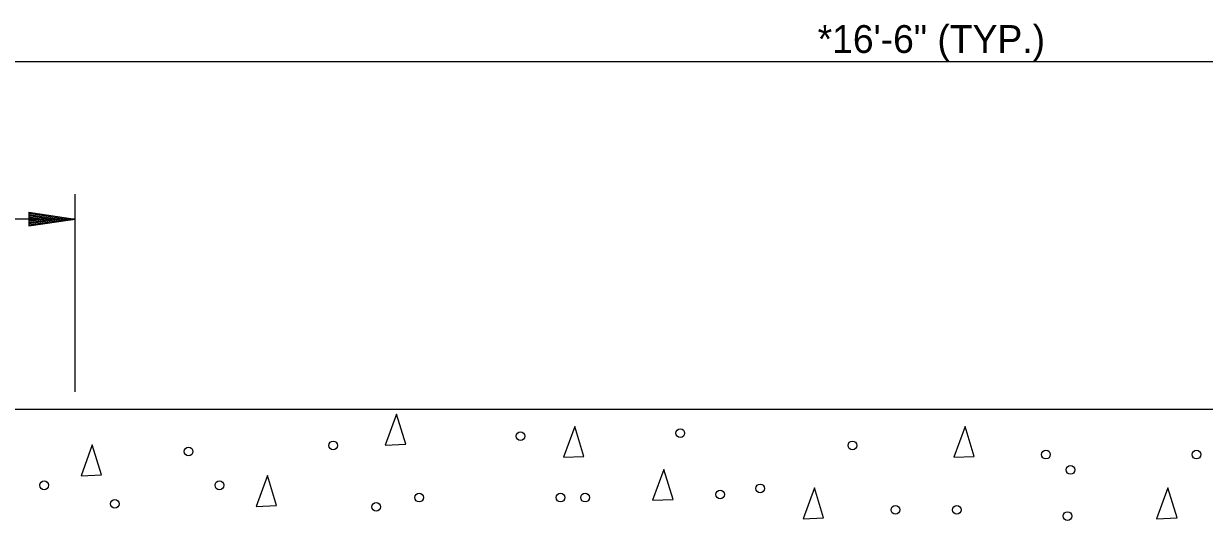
# Model space of a CAD drawing. Extents: x 635488 to 635865, y 290537 to 290973.
# Drawn here: x 635712.22 to 635737.65, y 290610.59 to 290621.3 of the extents above; entities that cross this region are included whole.
import ezdxf

# ---------------------------------------------------------------- set-up
doc = ezdxf.new("R2010")
doc.units = 0
doc.layers.add('Default', color=7, linetype='Continuous')

msp = doc.modelspace()

# ---------------------------------------------------------------- linework, layer by layer
at = {"layer": 'Default'}
for p, q in [((635709.583, 290620.481), (635750.831, 290620.481)), ((635713.333, 290613.362), (635713.333, 290617.625)), ((635712.334, 290617.236), (635713.334, 290617.086)), ((635712.334, 290617.236), (635712.334, 290616.936)), ((635713.333, 290617.086), (635709.583, 290617.086)), ((635712.334, 290617.211), (635713.167, 290617.086)), ((635712.334, 290617.186), (635712.994, 290617.086)), ((635712.334, 290617.161), (635712.829, 290617.086)), ((635712.334, 290617.136), (635712.659, 290617.086)), ((635712.334, 290617.111), (635712.492, 290617.086)), ((635712.334, 290616.936), (635713.334, 290617.086)), ((635712.334, 290617.038), (635712.659, 290617.086)), ((635712.334, 290616.986), (635712.994, 290617.086)), ((635712.334, 290616.961), (635713.167, 290617.086)), ((635712.334, 290617.011), (635712.829, 290617.086)), ((635712.334, 290617.063), (635712.492, 290617.086))]:
    msp.add_line(p, q, dxfattribs=at)
for points in [[(635659.586, 290612.987), (635750.831, 290612.987)], [(635720.254, 290612.878), (635720.011, 290612.216), (635720.451, 290612.233), (635720.254, 290612.878)], [(635724.091, 290612.613), (635723.849, 290611.951), (635724.289, 290611.968), (635724.091, 290612.613)], [(635732.496, 290612.613), (635732.256, 290611.951), (635732.696, 290611.968), (635732.496, 290612.613)], [(635713.702, 290612.218), (635713.459, 290611.553), (635713.899, 290611.571), (635713.702, 290612.218)], [(635726.011, 290611.688), (635725.769, 290611.024), (635726.208, 290611.041), (635726.011, 290611.688)], [(635717.474, 290611.556), (635717.232, 290610.891), (635717.672, 290610.909), (635717.474, 290611.556)], [(635729.253, 290611.291), (635729.011, 290610.626), (635729.451, 290610.644), (635729.253, 290611.291)], [(635736.865, 290611.291), (635736.623, 290610.626), (635737.063, 290610.644), (635736.865, 290611.291)]]:
    msp.add_lwpolyline(points, dxfattribs=at)
for centre in [(635722.924, 290612.407), (635726.365, 290612.473), (635715.776, 290612.075), (635718.887, 290612.208), (635730.071, 290612.208), (635734.24, 290612.009), (635737.483, 290612.009), (635734.769, 290611.678), (635712.666, 290611.347), (635716.438, 290611.347), (635720.74, 290611.082), (635723.784, 290611.082), (635724.313, 290611.082), (635727.225, 290611.148), (635728.085, 290611.281), (635714.188, 290610.95), (635719.813, 290610.884), (635730.997, 290610.817), (635732.321, 290610.817), (635734.703, 290610.685)]:
    msp.add_circle(centre, 0.0937, dxfattribs=at)

# ---------------------------------------------------------------- texts
msp.add_text('*16\'-6" (TYP.)', height=0.6, dxfattribs=at).set_placement((635729.323, 290620.665))

doc.saveas('drawing.dxf')
